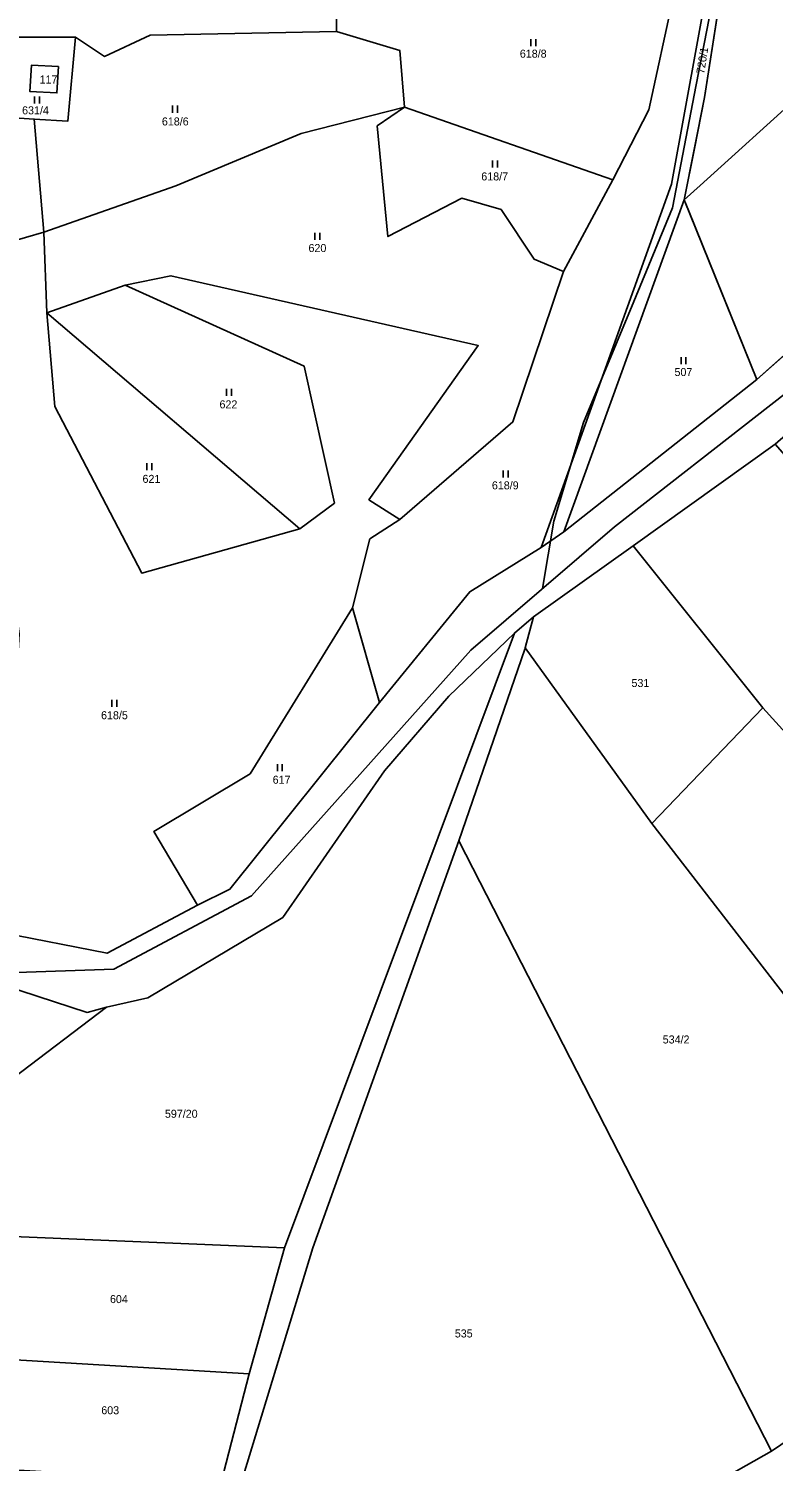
# Model space of a CAD drawing. Extents: x -590606 to -587796, y -1065936 to -1062515.
# Drawn here: x -589686.4 to -589528.2, y -1065384.3 to -1065080 of the extents above; entities that cross this region are included whole.
import ezdxf

# ---------------------------------------------------------------- set-up
doc = ezdxf.new("R2010")
doc.units = 0
for name, color, linetype in [('Cesty', 7, 'Continuous'), ('Místní komunikace', 7, 'Continuous'), ('Parcela nároku', 7, 'Continuous'), ('Vnější obvod_ Studené', 7, 'Continuous'), ('Vrstva 30', 7, 'Continuous')]:
    doc.layers.add(name, color=color, linetype=linetype)

msp = doc.modelspace()

# ---------------------------------------------------------------- linework, layer by layer
at = {"layer": 'Cesty'}
msp.add_lwpolyline([(-589577.24, -1065198.94), (-589574.86, -1065184.67), (-589568.53, -1065163.67), (-589557.88, -1065137.95), (-589549.66, -1065118.11), (-589544.6, -1065091.93), (-589540.17, -1065069.02), (-589539.27, -1065042.82), (-589539.37, -1065016.25), (-589537.8, -1065015.79)], dxfattribs=at)
at = {"layer": 'Místní komunikace'}
msp.add_lwpolyline([(-590032.24, -1065438.38), (-590006.45, -1065407.31), (-589942.84, -1065337.53), (-589895.42, -1065285.51), (-589869.8, -1065266.79), (-589828.89, -1065251.03), (-589784.72, -1065247.93), (-589748.82, -1065251.39), (-589723.97, -1065262.33), (-589705.87, -1065274.36), (-589691.01, -1065280.58), (-589668.31, -1065279.77), (-589639.11, -1065264.21), (-589592.5, -1065212.05), (-589561.97, -1065185.83), (-589495.54, -1065133.99), (-589439.02, -1065083.5)], dxfattribs=at)
at = {"layer": 'Parcela nároku'}
for points in [[(-589577.57, -1065190.24), (-589549.86, -1065113.03), (-589541.38, -1065066.73), (-589540.15, -1065017.98), (-589540.51, -1064976.01), (-589540.75, -1064971.67), (-589537.53, -1064968.54), (-589537.4, -1064973.3), (-589537.45, -1064983.64), (-589537.8, -1065015.79), (-589537.8, -1065019.01), (-589538.32, -1065047.17), (-589538.25, -1065064.22), (-589538.37, -1065066.07), (-589542.82, -1065094.63), (-589547.12, -1065116.37), (-589572.74, -1065186.9)], [(-589478.37, -1065016.09), (-589503.15, -1065036.55), (-589538.37, -1065066.07), (-589542.82, -1065094.63), (-589547.12, -1065116.37), (-589543.73, -1065113.31), (-589522.14, -1065093.79), (-589504.94, -1065078.24), (-589494.98, -1065069.24), (-589468.15, -1065044.98), (-589458.09, -1065038.68), (-589454.84, -1065036.64), (-589476.59, -1065010.77), (-589478.86, -1065012.72)], [(-589558.18, -1065064.74), (-589590.05, -1065069.91), (-589620.93, -1065074.85), (-589621.05, -1065080.6), (-589607.58, -1065084.63), (-589606.55, -1065096.67), (-589562.34, -1065112.16), (-589554.67, -1065097.26), (-589549.52, -1065073.43)], [(-589607.56, -1065184.27), (-589613.92, -1065188.4), (-589617.61, -1065203.04), (-589611.87, -1065223.17), (-589592.7, -1065199.64), (-589577.57, -1065190.24), (-589549.86, -1065113.03), (-589541.38, -1065066.73), (-589544.64, -1065069.18), (-589549.52, -1065073.43), (-589554.67, -1065097.26), (-589562.34, -1065112.16), (-589572.76, -1065131.63), (-589583.57, -1065163.54)], [(-589504.94, -1065078.24), (-589494.98, -1065069.24), (-589491.94, -1065073.46), (-589493.57, -1065074.64), (-589490.67, -1065078.66), (-589489.05, -1065077.46), (-589475.58, -1065096.14), (-589458.35, -1065084.21), (-589454.83, -1065089.29), (-589471.77, -1065101.42), (-589491.61, -1065118.9), (-589527.75, -1065151), (-589531.71, -1065154.52), (-589546.14, -1065118.8), (-589547.12, -1065116.37), (-589543.73, -1065113.31), (-589522.14, -1065093.79)], [(-589607.58, -1065084.63), (-589621.05, -1065080.6), (-589660.6, -1065081.39), (-589670.3, -1065085.92), (-589676.46, -1065081.84), (-589678.11, -1065099.65), (-589685.27, -1065099.24), (-589683.22, -1065123.23), (-589655.15, -1065113.41), (-589628.53, -1065102.3), (-589606.55, -1065096.67)], [(-589676.46, -1065081.84), (-589692.15, -1065081.84), (-589692.68, -1065098.77), (-589685.27, -1065099.24), (-589678.11, -1065099.65)], [(-589685.85, -1065087.78), (-589686.17, -1065093.39), (-589680.44, -1065093.66), (-589680.12, -1065088.07)], [(-589680.44, -1065093.66), (-589680.12, -1065088.07), (-589685.85, -1065087.78), (-589686.17, -1065093.39)], [(-589586.05, -1065118.45), (-589579.06, -1065129), (-589572.76, -1065131.63), (-589583.57, -1065163.54), (-589607.56, -1065184.27), (-589614.13, -1065180.1), (-589590.91, -1065147.35), (-589656.21, -1065132.5), (-589665.95, -1065134.52), (-589682.61, -1065140.39), (-589683.22, -1065123.23), (-589655.15, -1065113.41), (-589628.53, -1065102.3), (-589606.55, -1065096.67), (-589612.39, -1065100.68), (-589610.1, -1065124.19), (-589594.42, -1065116.05)], [(-589606.55, -1065096.67), (-589612.39, -1065100.68), (-589610.1, -1065124.19), (-589594.42, -1065116.05), (-589586.05, -1065118.45), (-589579.06, -1065129), (-589572.76, -1065131.63), (-589562.34, -1065112.16)], [(-589531.71, -1065154.52), (-589546.14, -1065118.8), (-589547.12, -1065116.37), (-589572.74, -1065186.9)], [(-589650.55, -1065266.18), (-589659.83, -1065250.55), (-589639.39, -1065238.29), (-589617.61, -1065203.04), (-589613.92, -1065188.4), (-589607.56, -1065184.27), (-589614.13, -1065180.1), (-589590.91, -1065147.35), (-589656.21, -1065132.5), (-589665.95, -1065134.52), (-589627.89, -1065151.73), (-589621.47, -1065180.8), (-589628.8, -1065186.3), (-589662.42, -1065195.68), (-589680.9, -1065160.28), (-589682.61, -1065140.39), (-589683.22, -1065123.23), (-589691.02, -1065125.53), (-589695.86, -1065128.94), (-589691.69, -1065159.39), (-589693.19, -1065172.46), (-589688.49, -1065208.59), (-589692.24, -1065271.98), (-589669.77, -1065276.4)], [(-589627.89, -1065151.73), (-589665.95, -1065134.52), (-589682.61, -1065140.39), (-589628.8, -1065186.3), (-589621.47, -1065180.8)], [(-589628.8, -1065186.3), (-589682.61, -1065140.39), (-589680.9, -1065160.28), (-589662.42, -1065195.68)], [(-589527.79, -1065168.29), (-589431.32, -1065278.11), (-589451.89, -1065302.84), (-589453.94, -1065305.16), (-589481.4, -1065278.29), (-589530.42, -1065224.3), (-589557.97, -1065189.9)], [(-589579.19, -1065204.99), (-589557.97, -1065189.9), (-589530.42, -1065224.3), (-589554.02, -1065248.84), (-589580.96, -1065211.55)], [(-589617.61, -1065203.04), (-589639.39, -1065238.29), (-589659.83, -1065250.55), (-589650.55, -1065266.18), (-589643.66, -1065262.81), (-589611.87, -1065223.17)], [(-589669.93, -1065287.88), (-589661.1, -1065285.91), (-589632.41, -1065268.81), (-589610.86, -1065237.66), (-589597.17, -1065221.79), (-589583.19, -1065208.42), (-589632.09, -1065339), (-589696.57, -1065336.27), (-589689.69, -1065302.87)], [(-589506.17, -1065310.71), (-589554.02, -1065248.84), (-589580.96, -1065211.55), (-589581.03, -1065211.81), (-589595.04, -1065252.55), (-589528.61, -1065382.21), (-589508.15, -1065368.32), (-589483.62, -1065339.41)], [(-589554.02, -1065248.84), (-589530.42, -1065224.3), (-589481.4, -1065278.29), (-589506.17, -1065310.71)], [(-589595.04, -1065252.55), (-589626.07, -1065338.96), (-589642.58, -1065393.12), (-589655.53, -1065450.77), (-589588.31, -1065425.97), (-589584.09, -1065421.06), (-589573.17, -1065407.41), (-589528.61, -1065382.21)], [(-589669.93, -1065287.88), (-589674.02, -1065288.97), (-589705.99, -1065278.61), (-589706.7, -1065336.75), (-589696.57, -1065336.27), (-589689.69, -1065302.87)], [(-589632.09, -1065339), (-589696.57, -1065336.27), (-589695.28, -1065362.4), (-589639.59, -1065365.74)], [(-589695.8, -1065385.76), (-589695.28, -1065362.4), (-589639.59, -1065365.74), (-589645.53, -1065388.75)], [(-589485.78, -1065388.71), (-589508.15, -1065368.32), (-589528.61, -1065382.21), (-589573.17, -1065407.41), (-589550.14, -1065435.35), (-589506.84, -1065414.13)]]:
    msp.add_lwpolyline(points, close=True, dxfattribs=at)
for points in [[(-589705.99, -1065278.61), (-589674.02, -1065288.97), (-589669.93, -1065287.88), (-589661.1, -1065285.91), (-589632.41, -1065268.81), (-589610.86, -1065237.66), (-589597.17, -1065221.79), (-589583.19, -1065208.42), (-589579.19, -1065204.99), (-589557.97, -1065189.9), (-589527.79, -1065168.29), (-589498.25, -1065142.61), (-589469.86, -1065115.16), (-589438.97, -1065089.22), (-589436.41, -1065087.3), (-589434.49, -1065085.87), (-589432.22, -1065084.17), (-589412.82, -1065071.17)], [(-589428.09, -1065070.14), (-589445.82, -1065082.83), (-589454.83, -1065089.29), (-589471.77, -1065101.42), (-589491.61, -1065118.9), (-589527.75, -1065151), (-589531.71, -1065154.52), (-589572.74, -1065186.9), (-589577.57, -1065190.24), (-589592.7, -1065199.64), (-589611.87, -1065223.17), (-589643.66, -1065262.81), (-589650.55, -1065266.18), (-589669.77, -1065276.4), (-589692.24, -1065271.98)], [(-589620.93, -1065074.85), (-589621.05, -1065080.6), (-589660.6, -1065081.39), (-589670.3, -1065085.92), (-589676.46, -1065081.84), (-589692.15, -1065081.84), (-589692.68, -1065098.77), (-589685.27, -1065099.24), (-589683.22, -1065123.23), (-589691.02, -1065125.53), (-589695.89, -1065126.71), (-589705.52, -1065107.06), (-589717.32, -1065085.65), (-589731.97, -1065078.6)], [(-589664.12, -1065549.07), (-589666.01, -1065532.92), (-589665.59, -1065493.46), (-589658.89, -1065445.55), (-589645.53, -1065388.75), (-589639.59, -1065365.74), (-589632.09, -1065339), (-589583.19, -1065208.42), (-589579.19, -1065204.99), (-589580.96, -1065211.55), (-589581.03, -1065211.81), (-589595.04, -1065252.55), (-589626.07, -1065338.96), (-589642.58, -1065393.12), (-589655.53, -1065450.77), (-589658.25, -1065472.24), (-589660.24, -1065489.59), (-589661.64, -1065518.72), (-589660.34, -1065537.96), (-589657.06, -1065558.69)]]:
    msp.add_lwpolyline(points, dxfattribs=at)
at = {"layer": 'Vnější obvod_ Studené'}
for p, q in [((-589542.82, -1065094.63), (-589538.37, -1065066.07)), ((-589544.97, -1065105.5), (-589542.82, -1065094.63)), ((-589471.77, -1065101.42), (-589531.71, -1065154.52)), ((-589547.12, -1065116.37), (-589544.97, -1065105.5)), ((-589531.71, -1065154.52), (-589547.12, -1065116.37))]:
    msp.add_line(p, q, dxfattribs=at)
at = {"layer": 'Vrstva 30'}
for p, q in [((-589579.7, -1065082.26), (-589579.7, -1065083.76)), ((-589578.68, -1065083.76), (-589578.68, -1065082.26)), ((-589685.19, -1065094.43), (-589685.19, -1065095.93)), ((-589684.17, -1065095.93), (-589684.17, -1065094.43)), ((-589655.88, -1065096.37), (-589655.88, -1065097.87)), ((-589654.85, -1065097.87), (-589654.85, -1065096.37)), ((-589587.88, -1065108.04), (-589587.88, -1065109.54)), ((-589586.85, -1065109.54), (-589586.85, -1065108.04)), ((-589625.61, -1065123.37), (-589625.61, -1065124.87)), ((-589624.58, -1065124.87), (-589624.58, -1065123.37)), ((-589547.81, -1065149.79), (-589547.81, -1065151.29)), ((-589546.79, -1065151.29), (-589546.79, -1065149.79)), ((-589644.37, -1065156.52), (-589644.37, -1065158.02)), ((-589643.34, -1065158.02), (-589643.34, -1065156.52)), ((-589661.3, -1065172.3), (-589661.3, -1065173.8)), ((-589660.28, -1065173.8), (-589660.28, -1065172.3)), ((-589585.59, -1065173.84), (-589585.59, -1065175.34)), ((-589584.57, -1065175.34), (-589584.57, -1065173.84)), ((-589668.77, -1065222.61), (-589668.77, -1065224.11)), ((-589667.74, -1065224.11), (-589667.74, -1065222.61)), ((-589633.57, -1065236.27), (-589633.57, -1065237.77)), ((-589632.55, -1065237.77), (-589632.55, -1065236.27))]:
    msp.add_line(p, q, dxfattribs=at)

# ---------------------------------------------------------------- texts
at = {"layer": 'Parcela nároku'}
for s, p in [('618/8', (-589582.07, -1065086.18)), ('117', (-589684.13, -1065091.67)), ('631/4', (-589687.84, -1065098.22)), ('618/6', (-589658.13, -1065100.58)), ('618/7', (-589590.26, -1065112.26)), ('620', (-589626.98, -1065127.47)), ('507', (-589549.21, -1065153.81)), ('622', (-589645.89, -1065160.68)), ('621', (-589662.25, -1065176.5)), ('618/9', (-589588.01, -1065177.88)), ('531', (-589558.35, -1065219.86)), ('618/5', (-589671.06, -1065226.71)), ('617', (-589634.59, -1065240.41)), ('534/2', (-589551.71, -1065295.58)), ('597/20', (-589657.49, -1065311.36)), ('604', (-589669.16, -1065350.73)), ('535', (-589595.89, -1065358.03)), ('603', (-589671.01, -1065374.34))]:
    msp.add_text(s, height=1.7, dxfattribs=at).set_placement(p)
msp.add_text('720/1', height=1.7, rotation=81, dxfattribs=at).set_placement((-589542.91, -1065089.7))

doc.saveas('drawing.dxf')
